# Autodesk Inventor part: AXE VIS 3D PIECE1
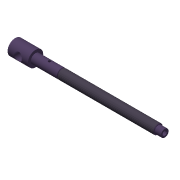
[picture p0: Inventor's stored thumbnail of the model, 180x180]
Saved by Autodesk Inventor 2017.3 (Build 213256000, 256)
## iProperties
Shininess: 21.0
Length Units: 11269
Angle Units: 11279
Time Units: 11290
Mass Units: 11283
Length Display Precision: 3
Angle Display Precision: 2
Created: 2001-10
Part Number: AXE VIS 3D PIECE1
Material: Générique
Document SubType Name: Modélisation
Designer: ajt
Density: 1 g/cm^3
Appearance: Lavande
Density: 0.0
Volumn: 0.0
Area: 0.0
PropertySet Name: Model Information
Control State: 0
Master: False
Checked Out: False
Author: ajt
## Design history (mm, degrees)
node "Plan de construction1"
extrude "ExtrusionBorgne1" new body distance "d2" = 32; taper "d3" = 0 deg
  node "Esquisse2" dims "d1" = 24
node "Plan de construction3"
node "Plan de construction9"
sketch "Esquisse3"
  geometry: C1 r 7.5 at (0, 0)
  constraints: 1 centre point
  dimensions: "d9" = 15 diameter of C1
extrude "ExtrusionBorgne2" join sketch "Esquisse3" distance "d10" = 37; taper "d11" = 0 deg
sketch "Esquisse4"
  geometry: 1 further point
node "Plan de construction15"
sketch "Esquisse5"
  geometry: L1 (212.952, 142.802)-(209.202, 142.802); L2 (213.702, 141.881)-(212.952, 142.802); L3 (214.452, 142.802)-(213.702, 141.881); L4 (364.282, 142.802)-(214.452, 142.802); L5 (365.202, 141.881)-(364.282, 142.802); L6 (365.202, 135.302)-(365.202, 141.881); L7 (209.202, 135.302)-(365.202, 135.302); L8 (209.202, 142.802)-(209.202, 135.302); L9 (209.202, 135.302)-(209.202, 136.302); L10 (209.202, 135.302)-(365.202, 135.302)
  constraints: 20 end point, 2 horizontal, 2 vertical, 1 collinear
  dimensions: "d15" = 3.75 horizontal distance of L1.start L7.start; "d17" = 156 distance of L7.start L6.start; "d19" = 135 deg angle of L5 L6; "d21" = 6.57985 distance of L5.start L6.start; "d23" = 7.5 vertical distance of L4.start L6.start; "d25" = 0.92015 vertical distance of L2.start L1.start; "d27" = 1.5 distance of L3.start L1.start (computed from mdtd19); "d29" = 0.75 horizontal distance of L3.start L2.start (= 0.05 x mdtd19); "d31" = 7.5 distance of L1.end L7.start
revolve "AngleRévolution1" sketch "Esquisse5" stored, may be unused: angle "d32" = 360 deg
sketch "Esquisse7"
  geometry: L1 (0, 7.5)-(0, -7.5) reference; 1 further point
  dimensions: "d63" = 22 distance from line of L1 point (22, 0)
node "Plan de construction5"
sketch "Esquisse8"
  geometry: C1 r 6 at (0, 0)
  constraints: 1 centre point
  dimensions: "d36" = 12 diameter of C1
extrude "ExtrusionBorgne3" join sketch "Esquisse8" distance "d37" = 10; taper "d38" = 0 deg
hole "AM_HOLE_0301DE_1" sketch "Esquisse4" diameter "d39" = 12.5; stored, may be unused: countersink angle "d43" = 60 deg, drill point angle "d45" = 118 deg; dims "d40" = 6, "d41" = 4, "d42" = 2, "d44" = 8
node "Esquisse10"
hole "AM_HOLE_SI0042_1" diameter "d49" = 7; stored, may be unused: countersink angle "d53" = 60 deg, drill point angle "d55" = 118 deg; dims "d50" = 6, "d51" = 4, "d52" = 2, "d54" = 8
hole "AM_HOLE_0301DE_2" sketch "Esquisse7" diameter "d56" = 4; stored, may be unused: countersink angle "d60" = 60 deg, drill point angle "d62" = 118 deg; dims "d57" = 6, "d58" = 4, "d59" = 2, "d61" = 8
feature "Filetage1" dims "d64" = 10, "d65" = 0
node "Solide1"
node "Corps solides"
node "Corps surfaciques"
other parameters: "mdtd19" = 15 [user parameter; used in 2 equation terms], "d0" = 24 (derived), "d4" = 0, "d5" = 0, "d6" = 0, "d8" = 15 (derived), "d12" = 0, "d14" = 3.75 (derived), "d16" = 156 (derived), "d18" = 135 deg (derived), "d20" = 6.57985 (derived), "d22" = 7.5 (derived), "d24" = 0.92015 (derived), "d26" = 1.5 (derived), "d28" = 0.75 (derived), "d30" = 7.5 (derived), "d33" = 0, "d34" = 0, "d35" = 12 (derived), "d46" = 0, "d47" = 0
